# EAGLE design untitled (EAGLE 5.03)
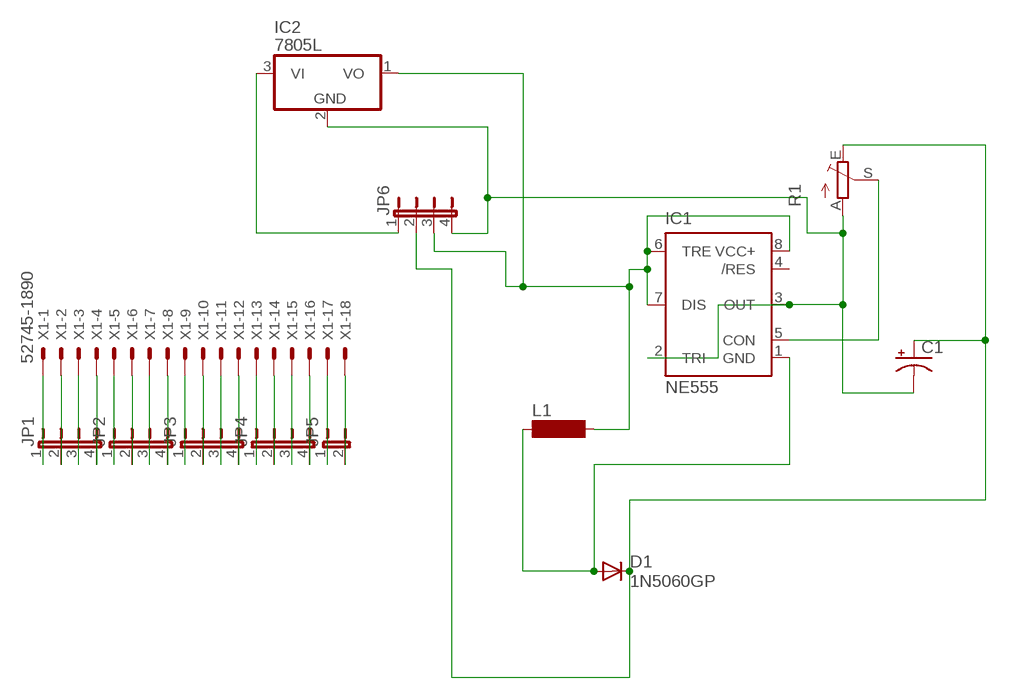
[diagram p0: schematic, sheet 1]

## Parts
C1  CPOL-USE3.5-10  [E3,5-10]
D1  1N5060GP  [DO15-12]
IC1  NE555  [DIL-08]
IC2  7805L  [TO92]
JP1  JP4E  [JP4]
JP2  JP4E  [JP4]
JP3  JP4E  [JP4]
JP4  JP4E  [JP4]
JP5  JP1E  [JP1]
JP6  JP4E  [JP4]
L1  SD12K100  [SD12K100]
R1  TRIM_EU-PT10S  [PT-10S]
X1  52745-1890  [52745-1890]

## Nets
N$1: JP1.1 X1.1
N$2: JP1.2 X1.2
N$3: JP1.3 X1.3
N$4: JP1.4 X1.4
N$5: JP2.1 X1.5
N$6: JP2.2 X1.6
N$7: JP2.3 X1.7
N$8: JP2.4 X1.8
N$9: JP3.1 X1.9
N$10: JP3.2 X1.10
N$11: JP3.3 X1.11
N$12: JP3.4 X1.12
N$13: JP4.1 X1.13
N$14: JP4.2 X1.14
N$15: JP4.3 X1.15
N$16: JP4.4 X1.16
N$17: JP5.1 X1.17
N$18: JP5.2 X1.18
N$19: C1.- IC1.2(TRI) IC1.3(OUT) IC2.2(GND) JP6.4 R1.A
N$20: IC1.5(CON) R1.S
N$21: IC1.6(TRE) IC1.7(DIS) IC1.8(VCC+) IC2.1(VO) JP6.3 L1.2
N$22: C1.+ D1.C JP6.2 R1.E
N$24: IC2.3(VI) JP6.1
N$25: D1.A IC1.1(GND) L1.1
Unconnected: IC1.4(/RES)

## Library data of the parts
C1 = rcl:CPOL-US: POLARIZED CAPACITOR, American symbol
D1 = diode:1N5060GP: DIODE
IC1 = st-microelectronics:NE555: General purpose bipolar Timer
IC2 = linear:78*: Positive VOLTAGE REGULATOR Source: http://cache.national.com/ds/LM/LM78L05.pdf http://www.fairchildsemi.com/ds/LM/LM7805.pdf
JP1-JP4 JP6 = jumper:JP4E: JUMPER
JP5 = jumper:JP1E: JUMPER
L1 = inductor-neosid:SD12: INDUCTOR
R1 = pot:TRIM_EU-: POTENTIOMETER
X1 = con-molex:52745-1890: FFC/FPC-to-Board 0.50mm (.020") SMT Top Contact Right Angle, ZIF, Style Receptacle 52745 / 52435 Source: http://www.molex.com/product/ffc/52745.html

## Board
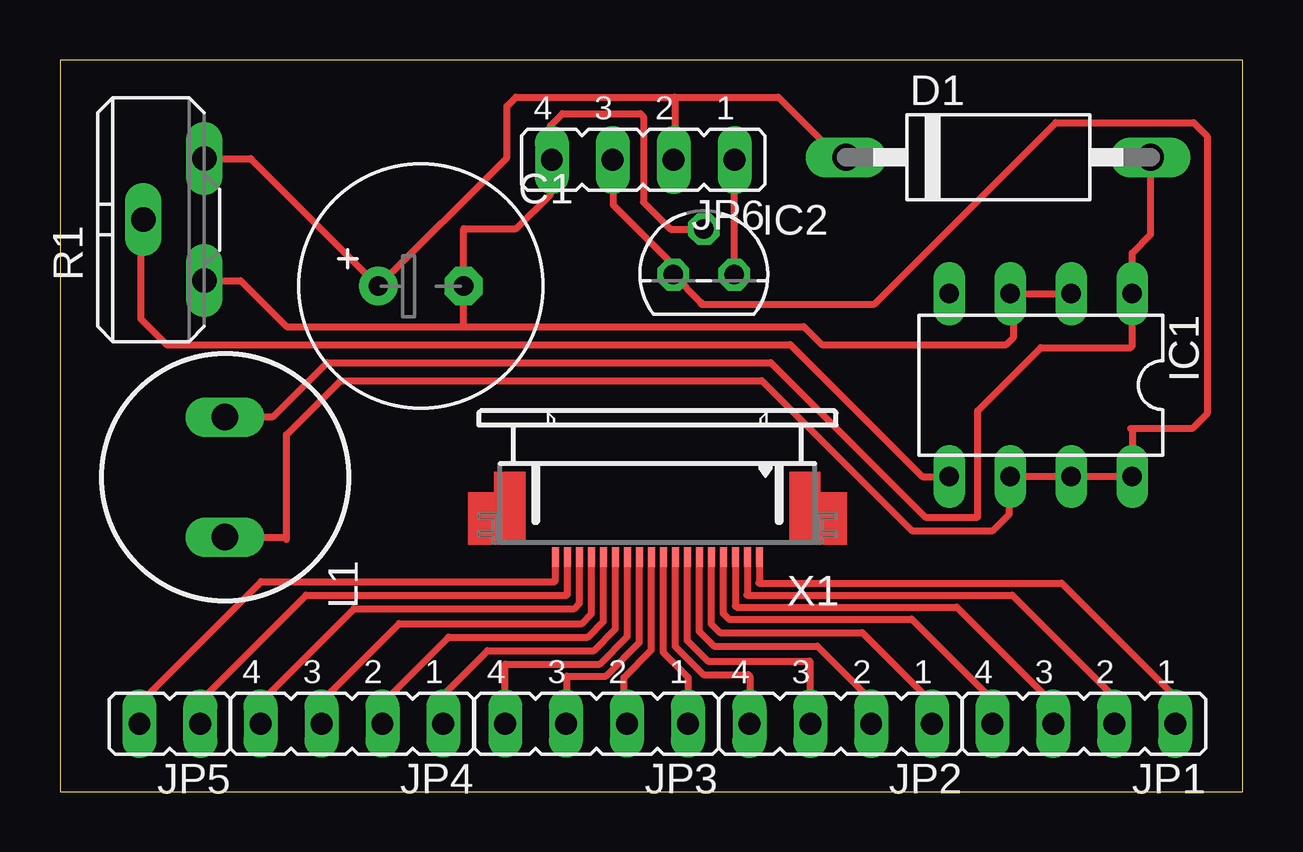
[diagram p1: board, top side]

Size 49.3 x 30.48 mm. Coordinates in mm from the lower left corner, seen from the top.
Outline: 0,0 49.3,0 49.3,30.48 0,30.48 0,0
Copper layers (1*16): Top 0.035mm / dielectric 1.5mm / Bottom 0.035mm
Design rules "default *": minimum track width 10mil, minimum drill 24mil, track to track 0.0051mm, track to pad 0.0051mm, pad to pad 0.0051mm, via to via 0.0051mm, smd to smd 0.2mm, copper to edge 40mil, drill to drill 8mil, minimum pad ring 10mil, minimum via ring 8mil, stop-mask expansion 4mil, vias tented up to drill 0mil, thermal gap 10mil

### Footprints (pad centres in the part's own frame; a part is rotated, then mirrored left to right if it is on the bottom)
E3,5-10 = drill 0.813 pad 1.6 round: + -1.778,0 | drill 0.813 pad 1.6 octagon: - 1.778,0
DO15-12 = drill 1.118 long: A 6.35,0; C -6.35,0
DIL-08 = drill 0.813 long: 1 -3.81,-3.81; 2 -1.27,-3.81; 3 1.27,-3.81; 4 3.81,-3.81; 5 3.81,3.81; 6 1.27,3.81; 7 -1.27,3.81; 8 -3.81,3.81
TO92 = drill 0.813 octagon: 1 -1.27,0; 2 0,1.905; 3 1.27,0
JP4 = drill 0.914 long: 1 -3.81,0; 2 -1.27,0; 3 1.27,0; 4 3.81,0
JP1 = drill 0.914 long: 1 0,-1.27; 2 0,1.27
SD12K100 = drill 1.1 long: 1 -2.5,0; 2 2.5,0
PT-10S = drill 1.016 long: A -2.54,-1.27; E 2.54,-1.27; S 0,1.27
52745-1890 = smd 0.3 x 0.8: 1 -4.25,2.5; 2 -3.75,2.5; 3 -3.25,2.5; 4 -2.75,2.5; 5 -2.25,2.5; 6 -1.75,2.5; 7 -1.25,2.5; 8 -0.75,2.5; 9 -0.25,2.5; 10 0.25,2.5; 11 0.75,2.5; 12 1.25,2.5; 13 1.75,2.5; 14 2.25,2.5; 15 2.75,2.5; 16 3.25,2.5; 17 3.75,2.5; 18 4.25,2.5

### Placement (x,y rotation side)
C1  15.04,21.06 0 top
D1  39.11,26.43 0 top
IC1  40.88,16.93 180 top
IC2  26.84,21.53 0 top
JP1  42.67,2.82 180 top
JP2  32.54,2.82 180 top
JP3  22.36,2.83 180 top
JP4  12.17,2.83 180 top
JP5  4.58,2.82 90 top
JP6  24.31,26.32 180 top
L1  6.88,13.1 270 top
R1  4.75,23.83 90 top
X1  24.9,12.28 180 top

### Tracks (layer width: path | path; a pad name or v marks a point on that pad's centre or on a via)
N$1
  Top 0.3: X1.1 29.15,8.71 29.12,8.69 41.75,8.69 46.5,3.94 46.5,2.84 JP1.1
N$2
  Top 0.3: X1.2 28.65,8.21 28.62,8.19 39.69,8.19 43.94,3.94 43.94,2.83 JP1.2
N$3
  Top 0.3: X1.3 28.15,7.72 28.19,7.69 37.38,7.69 41.31,3.75 41.31,2.92 JP1.3
N$4
  Top 0.3: X1.4 27.65,7.41 27.88,7.19 35.5,7.19 38.81,3.88 38.81,2.88 JP1.4
N$5
  Top 0.3: X1.5 27.15,6.97 27.5,6.62 33.44,6.62 36.44,3.62 36.44,2.91 JP2.1
N$6
  Top 0.3: X1.6 26.65,6.66 27.25,6.06 31.56,6.06 33.69,3.94 33.69,2.95 JP2.2
N$7
  Top 0.3: X1.7 26.15,6.29 27,5.44 31.25,5.44 31.25,2.85 JP2.3
N$8
  Top 0.3: X1.8 25.65,6.04 26.81,4.88 28.69,4.88 28.75,4.81 28.75,2.84 JP2.4
N$9
  Top 0.3: X1.9 25.15,5.79 26.19,4.75 26.19,2.84 JP3.1
N$10
  Top 0.3: X1.10 24.65,5.9 23.5,4.75 23.5,2.96 JP3.2
N$11
  Top 0.3: X1.11 24.15,6.21 22.75,4.81 21.12,4.81 21.12,2.86 JP3.3
N$12
  Top 0.3: X1.12 23.65,6.46 22.5,5.31 18.56,5.31 18.55,5.3 JP3.4
N$13
  Top 0.3: X1.13 23.15,6.78 22.25,5.88 17.81,5.88 16,4.06 16,2.85 JP4.1
N$14
  Top 0.3: X1.14 22.65,7.09 22,6.44 16.19,6.44 13.56,3.81 13.56,2.95 JP4.2
N$15
  Top 0.3: X1.15 22.15,7.4 21.75,7 14.12,7 11,3.88 11,2.93 JP4.3
N$16
  Top 0.3: X1.16 21.65,7.84 21.44,7.62 12.25,7.62 8.44,3.81 8.44,2.91 JP4.4
N$17
  Top 0.3: X1.17 21.15,8.21 21.12,8.19 10.25,8.19 5.88,3.81 5.88,2.85 JP5.1
N$18
  Top 0.3: X1.18 20.65,8.78 20.62,8.75 8.38,8.75 3.5,3.88 3.5,3.01 JP5.2
N$19
  Top 0.3: R1.A 7.52,21.29 9.44,19.38 16.81,19.38 | 16.81,19.38 31,19.38 31.75,18.62 39.44,18.62 39.75,18.94 39.75,20.6 IC1.3 IC1.2 | 16.81,19.38 16.82,19.39 C1.- 16.82,23.45 19.02,23.45 20.44,24.88 20.44,26.25 JP6.4 20.44,26.38 20.44,27.75 20.94,28.25 24.19,28.25 24.31,28.12 24.31,24.56 25.44,23.44 IC2.2 26.75,23.52
N$20
  Top 0.3: IC1.5 35.94,13.12 30.44,18.62 4.44,18.62 3.38,19.69 3.38,23.73 R1.S
N$21
  Top 0.3: L1.2 9.34,10.6 9.44,10.5 9.44,14.88 11.69,17.12 29.25,17.12 35.5,10.88 38.88,10.88 39.56,11.56 39.56,13.07 IC1.6 IC1.7 IC1.8 44.69,15.06 44.62,15.12 47.19,15.12 47.81,15.75 47.81,27.31 47.25,27.88 41.5,27.88 33.94,20.31 26.73,20.31 26.73,20.38 IC2.1 25.57,21.93 23.06,24.44 23.06,26.3 JP6.3
N$22
  Top 0.3: R1.E 7.96,26.37 C1.+ 18.62,26.42 18.62,28.56 19,28.94 25.62,28.94 | 25.62,28.94 29.94,28.94 32.45,26.43 D1.C | JP6.2 25.62,26.36 25.62,28.94
N$24
  Top 0.3: JP6.1 28.11,26.3 IC2.3
N$25
  Top 0.3: D1.A 45.46,23.21 44.69,22.44 IC1.1 44.69,18.57 44.62,18.5 40.88,18.5 38.25,15.88 38.25,11.44 36.06,11.44 29.62,17.88 11.12,17.88 8.88,15.62 6.9,15.62 L1.1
